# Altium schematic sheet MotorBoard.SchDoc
size B
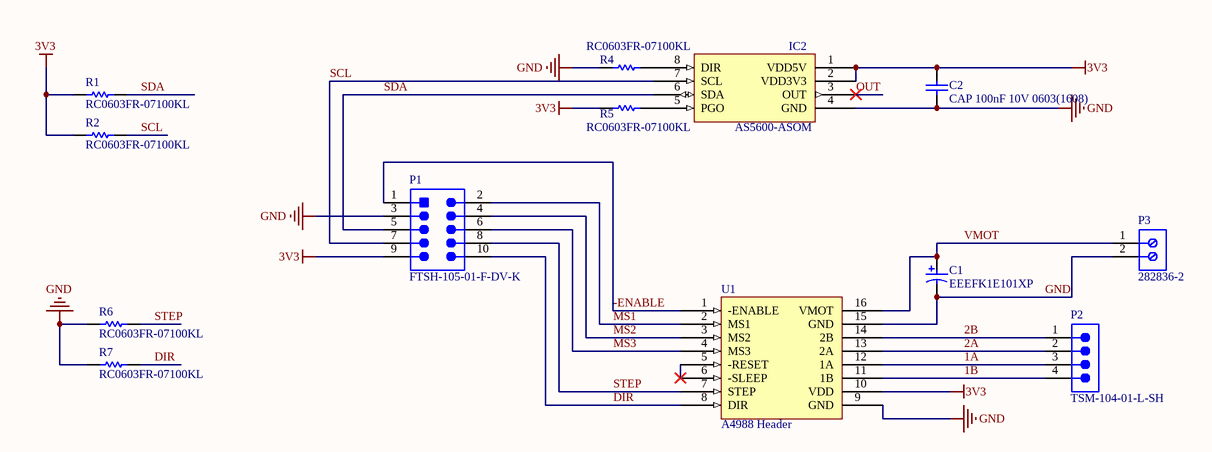
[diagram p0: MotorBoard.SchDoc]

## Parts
C1  EEEFK1E101XP  [PNSC-FK-V-D8_V]
C2  CAP 100nF 10V 0603(1608)  [CAPC0603(1608)100_M]
IC2  AS5600-ASOM  [SOIC127P600X175-8N]
P1  FTSH-105-01-F-DV-K  [SMTC-FTSH-105-01-L-DV-K_V]
P2  TSM-104-01-L-SH  [SMTC-TSM-104-01-X-SH]
P3  282836-2  [TECO-282836-2_V]
R1  RC0603FR-07100KL  [RESC1608X55X25ML10T15]
R2  RC0603FR-07100KL  [RESC1608X55X25ML10T15]
R4  RC0603FR-07100KL  [RESC1608X55X25ML10T15]
R5  RC0603FR-07100KL  [RESC1608X55X25ML10T15]
R6  RC0603FR-07100KL  [RESC1608X55X25ML10T15]
R7  RC0603FR-07100KL  [RESC1608X55X25ML10T15]
U1  A4988 Header  [A4988 Header-Footprint-1]

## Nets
3V3: C2.2 IC2.1(VDD5V) IC2.2(VDD3V3) P1.9 R1.1 R2.1 R5.1 U1.10(VDD)
GND: C1.2 C2.1 IC2.4(GND) P1.3 P3.2 R4.1 R6.1 R7.1 U1.9(GND) U1.15(GND)
1A: P2.3 U1.12(1A)
1B: P2.4 U1.11(1B)
2A: P2.2 U1.13(2A)
2B: P2.1 U1.14(2B)
-ENABLE: P1.1 U1.1(-ENABLE)
DIR: P1.10 R7.2 U1.8(DIR)
MS1: P1.2 U1.2(MS1)
MS2: P1.4 U1.3(MS2)
MS3: P1.6 U1.4(MS3)
OUT: IC2.3(OUT)
SCL: IC2.7(SCL) P1.7 R2.2
SDA: IC2.6(SDA) P1.5 R1.2
STEP: P1.8 R6.2 U1.7(STEP)
VMOT: C1.1 P3.1 U1.16(VMOT)
NetIC2_5: IC2.5(PGO) R5.2
NetIC2_8: IC2.8(DIR) R4.2
NetU1_5: U1.5(-RESET) U1.6(-SLEEP)

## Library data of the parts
C1 = CMP-2000-06206-1: Aluminum Electrolytic Capacitor, 100 uF, +/- 20%, 25 V, 2-Pin SMD (Size Code D8), -55 to 105 degC, RoHS, Tape and Reel; Manufacturer: Panasonic; Type: Can; Lifetime@Temperature: 2000Hrs@105°C; Capacitance: 100µF; Rated Voltage: 25V; Ripple Current: 280mA; Impedance: 0.34O
C2 = CMP-1035-02580-1: CAP 100nF 10V ±10% 0603 (1608 Metric) Thickness 1mm SMD; Tolerance: Â±10%; Case-EIA: 0603; Case-Metric: 1608
IC2 = CMP-00894-4: SENSOR ANGLE 360DEG SMD; Sensing Method: Hall Effect
P1 = CMP-2000-05352-1: Male Header, Pitch 1.27 mm, 2 x 5 Position, Height 6.12 mm, RoHS, Tube; Manufacturer: Samtec; Number of Positions: 10; Connector Type: Header,Shrouded; Number of Positions Loaded: All; Row Spacing: 0.050"(1.27mm); System: Connector
P2 = CMP-1024-00225-1: 0.025" SQ Post Header, Surface Mount, Horizontal, -55 to 125 degC, 2.54 mm Pitch, 4-Pin, Male, RoHS; Manufacturer: Samtec; Pitch: 2.54 mm
P3 = CMP-1684-00017-1: Female Header, Pitch 5 mm, 1 x 2 Position, Height 10 mm, Tail Length 3.5 mm, Rohs, Bulk; Manufacturer: TE Connectivity; Wire Gauge: 16-30AWG; Product Training Modules: Wire-to-BoardEurostyleTerminalBlocks; Clamp Material - Plating: Brass-NickelPlated; Voltage: 300V; Mating Orientation: HorizontalwithBoard; Current: 13.5A; Pitch: 0.197"(5.00mm); Screw Thread: M3; 3D Model: 282836-2.pdf; Other Names: 5ULV-02B / A98076; Dynamic Catalog: BuchananSeries; Number of Levels: 1; Torque - Screw: 0.68Nm(6Lb-In); Featured Product: EurostyleTerminalBlockConnectors; Positions Per Level: 2; Wire Termination: Screw-RisingCageClamp; System: Connector
R1 R2 R4-R7 = CMP-2100-03662-1: Chip Resistor, 100 KOhm, +/- 1%, 0.1 W, -55 to 155 degC, 0603 (1608 Metric), RoHS, Tape and Reel; Manufacturer: Yageo; Power Rating: 100mW; Voltage Rating: 50V; Temperature Coefficient: 100ppm/degreesC
U1 = CMP-00889-5: Female Header pins for the A4988 Motor Driver Carrier; Component Name: A4988 Headers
